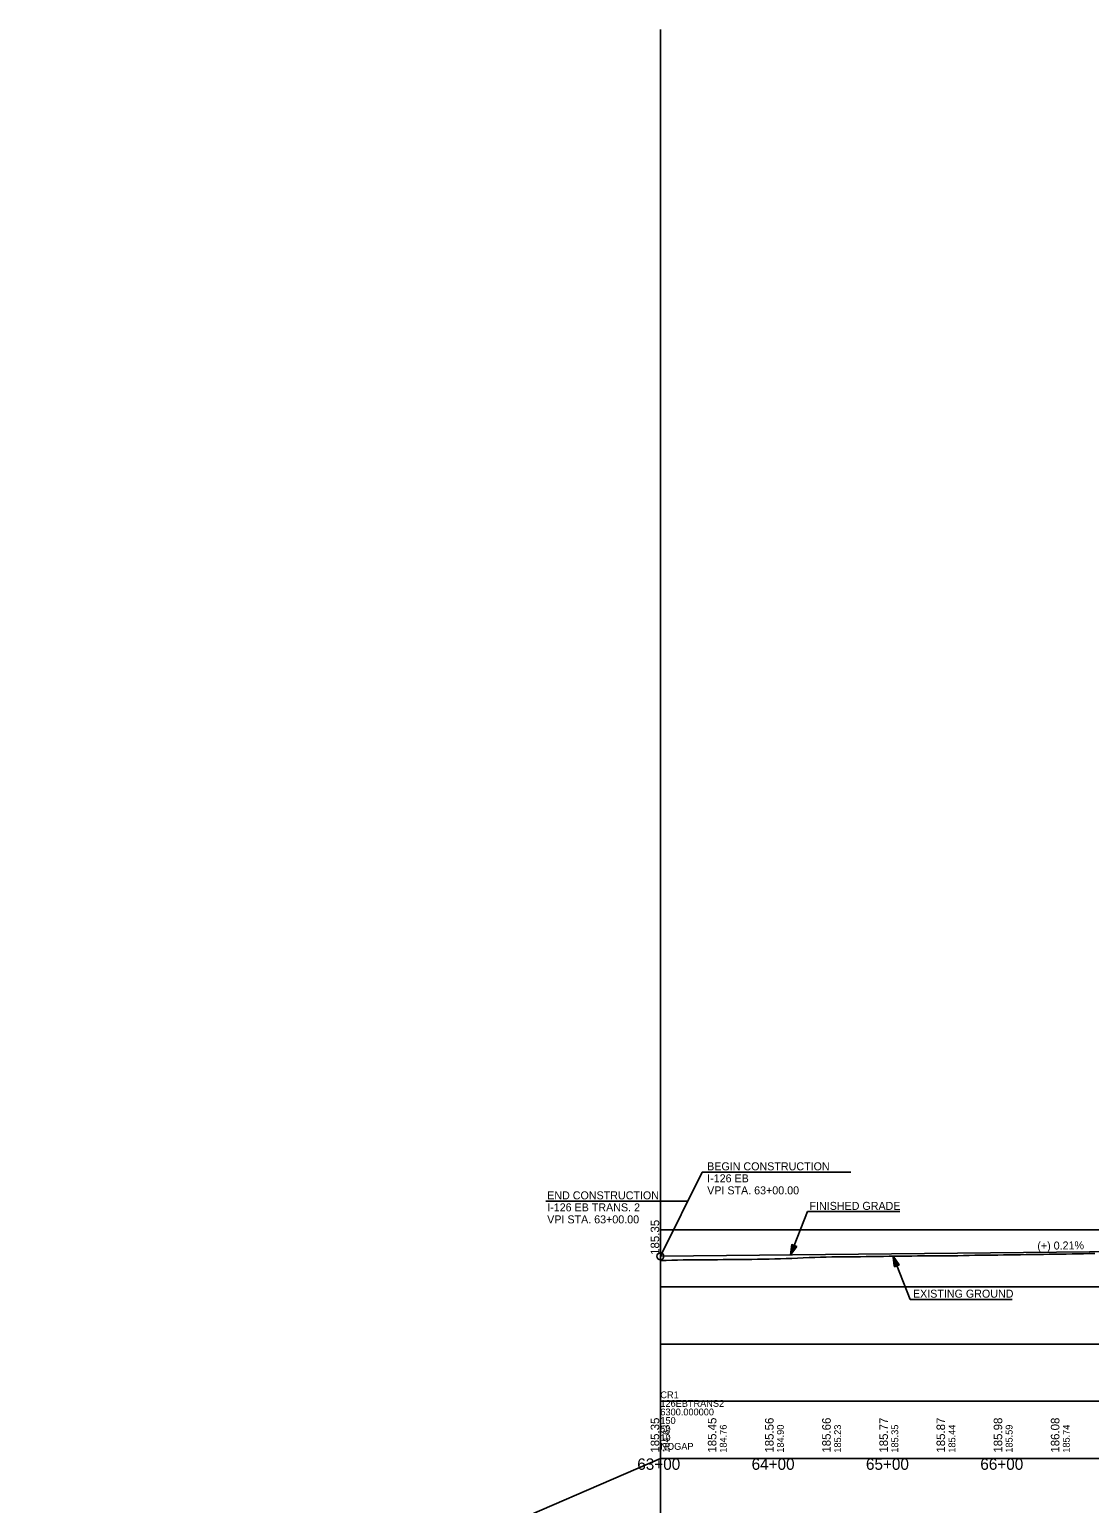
# Model space of a CAD drawing. Extents: x 69 to 2003113, y 512 to 837401.
# Drawn here: x 1893126 to 1894053, y 815469 to 816759 of the extents above; entities that cross this region are included whole.
import ezdxf

# ---------------------------------------------------------------- set-up
doc = ezdxf.new("R2010")
doc.units = 0
for name, color, linetype in [('BR_AUTO DIMENSION', 7, 'Continuous'), ('BR_BORDER LINES', 7, 'Continuous'), ('BR_CENTER LINE BASELINE', 7, 'Continuous'), ('BR_CONCRETE', 7, 'Continuous'), ('BR_GRID DOTS', 7, 'Continuous'), ('BR_GRID LINES', 7, 'Continuous'), ('BR_TEXT', 7, 'Continuous'), ('RD_HC_Points', 7, 'Continuous'), ('RD_PD_ALT1_TrvlWay', 7, 'Continuous'), ('RD_SHT_ID', 7, 'Continuous'), ('RD_SHT_IplotShp', 7, 'Continuous')]:
    doc.layers.add(name, color=color, linetype=linetype)

msp = doc.modelspace()

# ---------------------------------------------------------------- linework, layer by layer
at = {"layer": 'BR_AUTO DIMENSION'}
for p, q in [((1893677.5, 815508.6), (1893677.5, 816758.6)), ((1893677.5, 815708.6), (1894947.4, 815708.6)), ((1893677.5, 815658.6), (1894947.4, 815658.6)), ((1893677.5, 815608.6), (1894947.4, 815608.6)), ((1893677.5, 815558.6), (1894947.4, 815558.6)), ((1893677.5, 815508.6), (1891237.4, 814453.4)), ((1893677.5, 815508.6), (1894947.4, 815508.6))]:
    msp.add_line(p, q, dxfattribs=at)
at = {"layer": 'BR_BORDER LINES'}
for q in [(1893677.5, 816758.6), (1894977.5, 815508.6), (1893677.5, 814258.6)]:
    msp.add_line((1893677.5, 815508.6), q, dxfattribs=at)
at = {"layer": 'BR_CENTER LINE BASELINE'}
msp.add_circle((1893677.5, 815685.4), 3, dxfattribs=at)
at = {"layer": 'BR_GRID DOTS'}
for points in [[(1893677.5, 815685.4), (1893713.9, 815759)], [(1893713.9, 815759), (1893844.2, 815759)], [(1893577.4, 815733.6), (1893701.4, 815733.6)]]:
    msp.add_lwpolyline(points, dxfattribs=at)
at = {"layer": 'BR_GRID LINES'}
msp.add_line((1893677.5, 815685.4), (1894877.6, 815697.9), dxfattribs=at)
at = {"layer": 'BR_TEXT'}
msp.add_lwpolyline([(1893677.5, 815681.8), (1893682.5, 815681.8), (1893687.5, 815682), (1893692.5, 815682.1), (1893697.5, 815682.2), (1893702.5, 815682.2), (1893707.5, 815682.3), (1893712.5, 815682.3), (1893717.5, 815682.3), (1893722.5, 815682.4), (1893727.5, 815682.4), (1893732.5, 815682.5), (1893737.5, 815682.5), (1893742.5, 815682.6), (1893747.5, 815682.6), (1893752.5, 815682.7), (1893757.5, 815682.7), (1893762.5, 815682.8), (1893767.5, 815682.9), (1893772.5, 815683), (1893777.5, 815683.1), (1893782.5, 815683.3), (1893787.5, 815683.4), (1893792.5, 815683.6), (1893797.5, 815683.9), (1893802.5, 815684.1), (1893807.5, 815684.2), (1893812.5, 815684.3), (1893817.5, 815684.5), (1893822.5, 815684.6), (1893827.5, 815684.8), (1893832.5, 815684.9), (1893837.5, 815685), (1893842.5, 815685), (1893847.5, 815685), (1893852.5, 815685), (1893857.5, 815685.1), (1893862.5, 815685.1), (1893867.5, 815685.2), (1893872.5, 815685.3), (1893877.5, 815685.4), (1893882.5, 815685.5), (1893887.5, 815685.5), (1893892.5, 815685.6), (1893897.5, 815685.6), (1893902.5, 815685.7), (1893907.5, 815685.8), (1893912.5, 815685.8), (1893917.5, 815685.8), (1893922.5, 815685.8), (1893927.5, 815685.8), (1893932.5, 815685.9), (1893937.5, 815685.9), (1893942.5, 815686.1), (1893947.5, 815686.2), (1893952.5, 815686.3), (1893957.5, 815686.3), (1893962.5, 815686.4), (1893967.5, 815686.4), (1893972.5, 815686.5), (1893977.5, 815686.6), (1893982.5, 815686.7), (1893987.5, 815686.8), (1893992.5, 815686.8), (1893997.5, 815686.9), (1894002.5, 815686.9), (1894007.5, 815687), (1894012.5, 815687.1), (1894017.5, 815687.2), (1894022.5, 815687.2), (1894027.5, 815687.3), (1894032.5, 815687.4), (1894037.5, 815687.5), (1894042.5, 815687.6), (1894047.5, 815687.6), (1894052.5, 815687.7), (1894057.5, 815687.7)], dxfattribs=at)
at = {"layer": 'RD_PD_ALT1_TrvlWay'}
for p, q in [((1893791.3, 815686.6), (1893806.2, 815724.5)), ((1893806.2, 815724.5), (1893887, 815724.5)), ((1893791.3, 815686.6), (1893792.5, 815695.8)), ((1893791.3, 815686.6), (1893792.5, 815695.8)), ((1893794.6, 815694.9), (1893791.3, 815686.6)), ((1893794.6, 815694.9), (1893791.3, 815686.6)), ((1893791.3, 815686.6), (1893796.7, 815694.1)), ((1893791.3, 815686.6), (1893796.7, 815694.1)), ((1893792.5, 815695.8), (1893796.7, 815694.1)), ((1893792.5, 815695.8), (1893796.7, 815694.1)), ((1893881, 815685.5), (1893895.9, 815647.5)), ((1893884.3, 815677.1), (1893881, 815685.5)), ((1893881, 815685.5), (1893886.4, 815677.9)), ((1893881, 815685.5), (1893882.2, 815676.3)), ((1893882.2, 815676.3), (1893886.4, 815677.9)), ((1893895.9, 815647.5), (1893985.1, 815647.5))]:
    msp.add_line(p, q, dxfattribs=at)
for points in [[(1893794.5, 815694.9), (1893791.4, 815687.1), (1893794.4, 815694.9), (1893791.5, 815687.5), (1893794.3, 815694.9), (1893791.5, 815687.7), (1893794.2, 815695), (1893791.5, 815688.1), (1893794.2, 815695), (1893791.6, 815688.5), (1893794, 815695.1), (1893791.7, 815689.1), (1893793.9, 815695.1), (1893791.8, 815689.5), (1893793.8, 815695.1), (1893791.8, 815689.9), (1893793.7, 815695.1), (1893791.9, 815690.3), (1893793.7, 815695.2), (1893791.9, 815690.7), (1893793.5, 815695.2), (1893792, 815691.2), (1893793.4, 815695.3), (1893792.1, 815691.8), (1893793.3, 815695.3), (1893792.1, 815692.2), (1893793.2, 815695.4), (1893792.2, 815692.8), (1893793.1, 815695.4), (1893792.3, 815693.3), (1893793, 815695.5), (1893792.3, 815693.8), (1893792.9, 815695.5), (1893792.4, 815694.2), (1893792.8, 815695.6), (1893792.4, 815694.6), (1893792.7, 815695.6), (1893792.5, 815695.2), (1893792.6, 815695.6)], [(1893794.5, 815694.9), (1893791.4, 815687.1), (1893794.4, 815694.9), (1893791.5, 815687.5), (1893794.3, 815694.9), (1893791.5, 815687.7), (1893794.2, 815695), (1893791.5, 815688.1), (1893794.2, 815695), (1893791.6, 815688.5), (1893794, 815695.1), (1893791.7, 815689.1), (1893793.9, 815695.1), (1893791.8, 815689.5), (1893793.8, 815695.1), (1893791.8, 815689.9), (1893793.7, 815695.1), (1893791.9, 815690.3), (1893793.7, 815695.2), (1893791.9, 815690.7), (1893793.5, 815695.2), (1893792, 815691.2), (1893793.4, 815695.3), (1893792.1, 815691.8), (1893793.3, 815695.3), (1893792.1, 815692.2), (1893793.2, 815695.4), (1893792.2, 815692.8), (1893793.1, 815695.4), (1893792.3, 815693.3), (1893793, 815695.5), (1893792.3, 815693.8), (1893792.9, 815695.5), (1893792.4, 815694.2), (1893792.8, 815695.6), (1893792.4, 815694.6), (1893792.7, 815695.6), (1893792.5, 815695.2), (1893792.6, 815695.6)], [(1893791.6, 815687.1), (1893794.6, 815694.8), (1893791.7, 815687.3), (1893794.7, 815694.8), (1893791.9, 815687.6), (1893794.8, 815694.8), (1893792.1, 815687.8), (1893794.9, 815694.7), (1893792.3, 815688.1), (1893794.9, 815694.7), (1893792.4, 815688.3), (1893795, 815694.7), (1893792.7, 815688.6), (1893795.1, 815694.7), (1893792.9, 815689), (1893795.2, 815694.6), (1893793.1, 815689.3), (1893795.3, 815694.6), (1893793.3, 815689.6), (1893795.4, 815694.6), (1893793.6, 815689.9), (1893795.5, 815694.5), (1893793.8, 815690.3), (1893795.5, 815694.5), (1893794.1, 815690.7), (1893795.6, 815694.5), (1893794.4, 815691), (1893795.7, 815694.5), (1893794.7, 815691.4), (1893795.8, 815694.4), (1893794.9, 815691.8), (1893795.9, 815694.3), (1893795.1, 815692.1), (1893796, 815694.2), (1893795.4, 815692.4), (1893796, 815694.2), (1893795.7, 815692.9), (1893796.2, 815694.2), (1893795.8, 815693.1), (1893796.3, 815694.2), (1893796, 815693.3), (1893796.4, 815694), (1893796.5, 815694.1), (1893796.4, 815694.1)], [(1893791.6, 815687.1), (1893794.6, 815694.8), (1893791.7, 815687.3), (1893794.7, 815694.8), (1893791.9, 815687.6), (1893794.8, 815694.8), (1893792.1, 815687.8), (1893794.9, 815694.7), (1893792.3, 815688.1), (1893794.9, 815694.7), (1893792.4, 815688.3), (1893795, 815694.7), (1893792.7, 815688.6), (1893795.1, 815694.7), (1893792.9, 815689), (1893795.2, 815694.6), (1893793.1, 815689.3), (1893795.3, 815694.6), (1893793.3, 815689.6), (1893795.4, 815694.6), (1893793.6, 815689.9), (1893795.5, 815694.5), (1893793.8, 815690.3), (1893795.5, 815694.5), (1893794.1, 815690.7), (1893795.6, 815694.5), (1893794.4, 815691), (1893795.7, 815694.5), (1893794.7, 815691.4), (1893795.8, 815694.4), (1893794.9, 815691.8), (1893795.9, 815694.3), (1893795.1, 815692.1), (1893796, 815694.2), (1893795.4, 815692.4), (1893796, 815694.2), (1893795.7, 815692.9), (1893796.2, 815694.2), (1893795.8, 815693.1), (1893796.3, 815694.2), (1893796, 815693.3), (1893796.4, 815694), (1893796.5, 815694.1), (1893796.4, 815694.1)], [(1893884.2, 815677.2), (1893881.1, 815685), (1893884.1, 815677.1), (1893881.2, 815684.6), (1893884, 815677.1), (1893881.2, 815684.3), (1893883.9, 815677.1), (1893881.2, 815684), (1893883.8, 815677), (1893881.3, 815683.5), (1893883.7, 815677), (1893881.4, 815683), (1893883.6, 815676.9), (1893881.4, 815682.6), (1893883.5, 815676.9), (1893881.5, 815682.1), (1893883.4, 815676.9), (1893881.5, 815681.7), (1893883.4, 815676.8), (1893881.6, 815681.4), (1893883.2, 815676.8), (1893881.6, 815680.9), (1893883.1, 815676.7), (1893881.8, 815680.3), (1893883, 815676.7), (1893881.8, 815679.8), (1893882.9, 815676.6), (1893881.8, 815679.2), (1893882.8, 815676.6), (1893881.9, 815678.7), (1893882.7, 815676.5), (1893882, 815678.3), (1893882.6, 815676.5), (1893882, 815677.9), (1893882.5, 815676.4), (1893882.1, 815677.4), (1893882.4, 815676.5), (1893882.2, 815676.8), (1893882.3, 815676.5)], [(1893881.2, 815684.9), (1893884.3, 815677.2), (1893881.4, 815684.7), (1893884.4, 815677.3), (1893881.5, 815684.4), (1893884.5, 815677.2), (1893881.7, 815684.2), (1893884.5, 815677.3), (1893881.9, 815684), (1893884.6, 815677.3), (1893882.1, 815683.7), (1893884.7, 815677.3), (1893882.3, 815683.4), (1893884.8, 815677.4), (1893882.6, 815683.1), (1893884.9, 815677.4), (1893882.8, 815682.7), (1893885, 815677.4), (1893883, 815682.4), (1893885.1, 815677.5), (1893883.2, 815682.1), (1893885.1, 815677.5), (1893883.5, 815681.8), (1893885.2, 815677.6), (1893883.8, 815681.3), (1893885.3, 815677.6), (1893884, 815681), (1893885.4, 815677.6), (1893884.3, 815680.6), (1893885.5, 815677.6), (1893884.6, 815680.2), (1893885.5, 815677.7), (1893884.8, 815679.9), (1893885.6, 815677.8), (1893885, 815679.6), (1893885.7, 815677.8), (1893885.3, 815679.2), (1893885.9, 815677.8), (1893885.5, 815678.9), (1893886, 815677.8), (1893885.7, 815678.7), (1893886.1, 815678), (1893886.2, 815677.9), (1893886.1, 815678)]]:
    msp.add_lwpolyline(points, dxfattribs=at)

# ---------------------------------------------------------------- texts
at = {"layer": 'BR_BORDER LINES'}
for s, p in [('CR1', (1893677.5, 815561.2)), ('6300.000000', (1893677.5, 815546.2)), ('126EBTRANS2', (1893677.5, 815553.7)), ('150', (1893677.5, 815538.7)), ('50', (1893677.5, 815531.2)), ('10', (1893677.5, 815523.7)), ('NOGAP', (1893677.5, 815516.1))]:
    msp.add_text(s, height=6, dxfattribs=at).set_placement(p)
at = {"layer": 'BR_CENTER LINE BASELINE'}
msp.add_text('(+) 0.21%', height=7, rotation=0.5995, dxfattribs=at).set_placement((1894007.2, 815691.1))
at = {"layer": 'BR_CONCRETE'}
for s, p in [('184.90', (1893785.5, 815513.6)), ('185.35', (1893885.5, 815513.6)), ('185.44', (1893935.5, 815513.6)), ('185.74', (1894035.5, 815513.6)), ('184.63', (1893685.5, 815513.6)), ('184.76', (1893735.5, 815513.6)), ('185.23', (1893835.5, 815513.6)), ('185.59', (1893985.5, 815513.6))]:
    msp.add_text(s, height=6, rotation=90, dxfattribs=at).set_placement(p)
at = {"layer": 'RD_HC_Points'}
for s, p in [('185.35', (1893676.5, 815686.6)), ('185.35', (1893676.5, 815513.6)), ('185.45', (1893726.5, 815513.6)), ('185.56', (1893776.5, 815513.6)), ('185.66', (1893826.5, 815513.6)), ('185.77', (1893876.5, 815513.6)), ('185.87', (1893926.5, 815513.6)), ('185.98', (1893976.5, 815513.6)), ('186.08', (1894026.5, 815513.6))]:
    msp.add_text(s, height=7.5, rotation=90, dxfattribs=at).set_placement(p)
at = {"layer": 'RD_PD_ALT1_TrvlWay'}
for s, p in [('FINISHED GRADE', (1893807.9, 815726)), ('EXISTING GROUND', (1893898.4, 815649.2))]:
    msp.add_text(s, height=7, dxfattribs=at).set_placement(p)
at = {"layer": 'RD_SHT_ID'}
for s, p in [('63+00', (1893657.3, 815498.6)), ('64+00', (1893757.3, 815498.6)), ('65+00', (1893857.3, 815498.6)), ('66+00', (1893957.3, 815498.6))]:
    msp.add_text(s, height=10, dxfattribs=at).set_placement(p)
at = {"layer": 'RD_SHT_IplotShp'}
for s, p in [('BEGIN CONSTRUCTION', (1893718.4, 815760.6)), ('I-126 EB', (1893718.4, 815750.1)), ('VPI STA. 63+00.00', (1893718.4, 815739.6)), ('END CONSTRUCTION', (1893578.5, 815735.2)), ('I-126 EB TRANS. 2', (1893578.5, 815724.7)), ('VPI STA. 63+00.00', (1893578.5, 815714.2))]:
    msp.add_text(s, height=7, dxfattribs=at).set_placement(p)

doc.saveas('drawing.dxf')
